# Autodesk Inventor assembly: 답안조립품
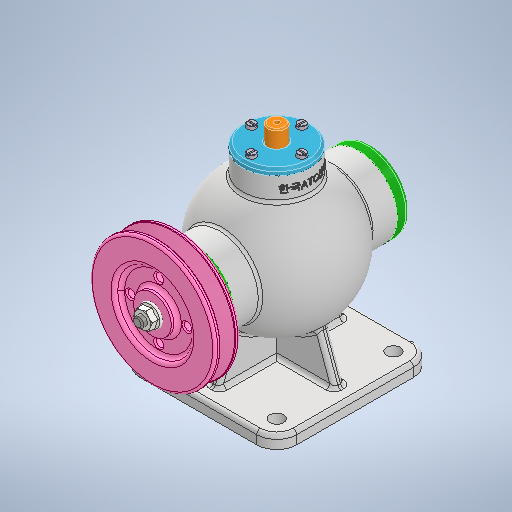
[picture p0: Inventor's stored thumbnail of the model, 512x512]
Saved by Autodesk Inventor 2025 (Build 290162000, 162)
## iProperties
Created: 2024-07
Part Number: 답안조립품
Document SubType Name: Assembly
Designer: anfro
Author: anfro
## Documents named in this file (15)
- D:\Desktop\740708V1011\답안조립품.iam
- D:\Desktop\740708V1011\V-벨트풀리\V-벨트풀리.ipt
- D:\Desktop\740708V1011\너트 M8\너트 M8.ipt
- D:\Desktop\740708V1011\뒤커버\뒤커버.ipt
- D:\Desktop\740708V1011\베어링- 6202\베어링- 6202.ipt
- D:\Desktop\740708V1011\본체.ipt
- D:\Desktop\740708V1011\볼트 M4 x 12\볼트 M4 x 12.ipt
- D:\Desktop\740708V1011\볼트 M4 x 16\볼트 M4 x 16.ipt
- D:\Desktop\740708V1011\상부커버\상부커버.ipt
- D:\Desktop\740708V1011\슬라이드\슬라이드.ipt
- D:\Desktop\740708V1011\앞커버\앞커버.ipt
- D:\Desktop\740708V1011\오일실 15 30 7\오일실 15 30 7.ipt
- D:\Desktop\740708V1011\칼라\칼라.ipt
- D:\Desktop\740708V1011\키 4 x 4 x 12\키 4 x 4 x 12.ipt
- D:\Desktop\740708V1011\편심축\편심축.ipt
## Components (1 placed, 1 different names)
1. V-벨트풀리:1 — 각도:2
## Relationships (1: Angle 1)
- 각도:2 [Angle]: V-벨트풀리:1
